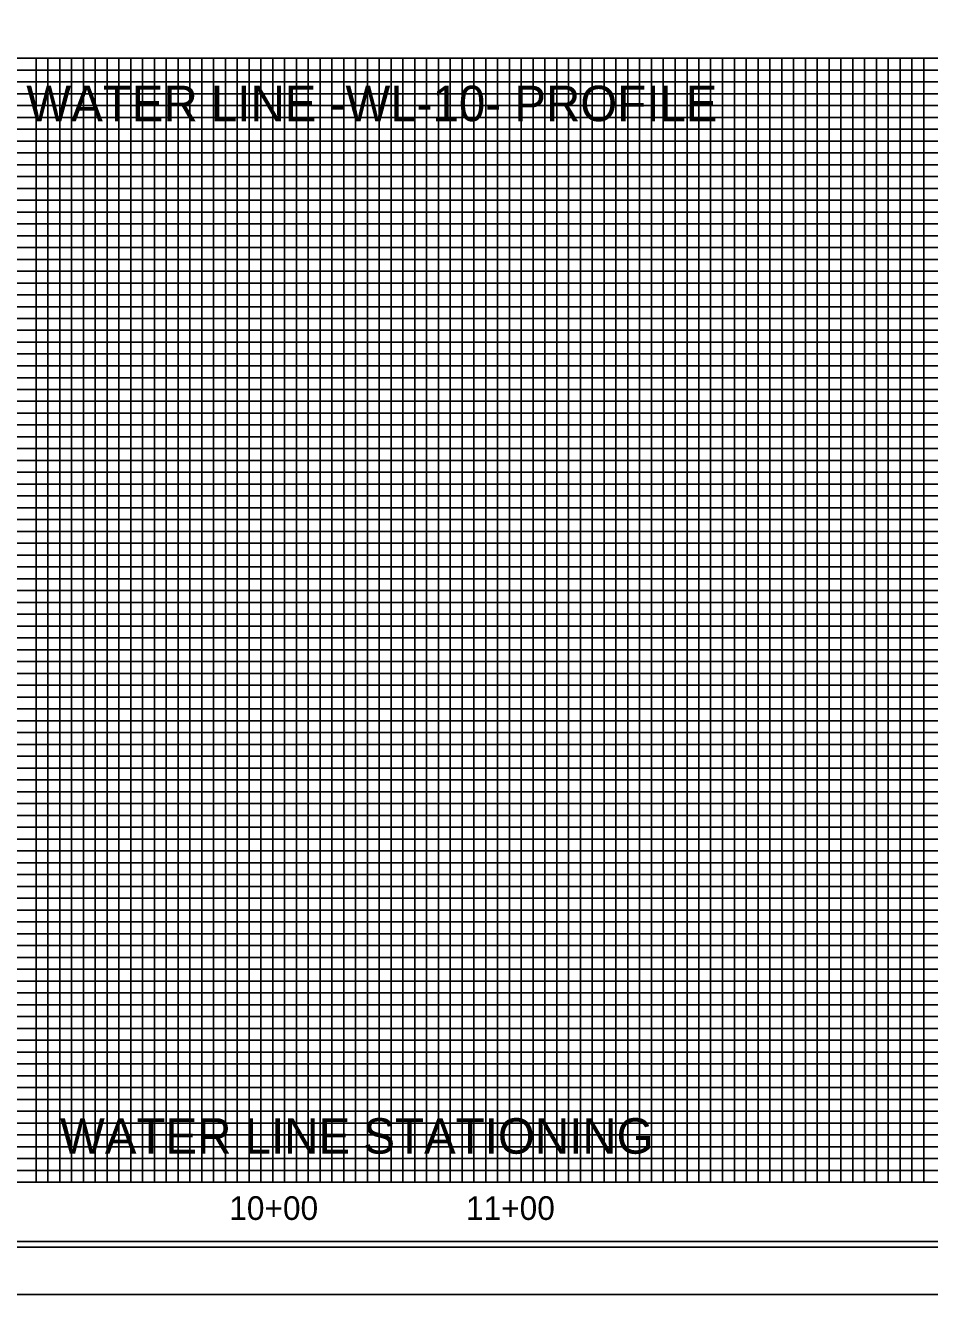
# Model space of a CAD drawing. Extents: x 0 to 4772457, y -312190 to 1506.
# Drawn here: x 1.547 to 2.184, y 0.008 to 0.902 of the extents above; entities that cross this region are included whole.
import ezdxf

# ---------------------------------------------------------------- set-up
doc = ezdxf.new("R2010")
doc.units = 0
for name, color, linetype in [('Exist Mini Skip Lane Lines', 7, 'Continuous'), ('Old_Level_38', 7, 'Continuous'), ('Old_Level_57', 7, 'Continuous'), ('Old_Level_63', 7, 'Continuous'), ('Table of Operation CELL', 7, 'Continuous')]:
    doc.layers.add(name, color=color, linetype=linetype)

msp = doc.modelspace()

# ---------------------------------------------------------------- linework, layer by layer
at = {"layer": 'Exist Mini Skip Lane Lines'}
for p, q in [((0.30499, 0.8375), (2.59666, 0.8375)), ((2.80499, 0.75416), (0.30499, 0.75416)), ((0.30499, 0.67083), (2.80499, 0.67083)), ((2.80499, 0.5875), (0.30499, 0.5875)), ((0.30499, 0.50416), (2.80499, 0.50416)), ((2.80499, 0.42083), (0.30499, 0.42083)), ((0.30499, 0.3375), (2.80499, 0.3375)), ((2.80499, 0.25416), (0.30499, 0.25416)), ((0.30499, 0.17083), (2.80499, 0.17083))]:
    msp.add_line(p, q, dxfattribs=at)
for points in [[(1.59666, 0.0875), (1.59666, 0.87916), (1.67999, 0.87916), (1.67999, 0.0875)], [(1.76333, 0.0875), (1.76333, 0.87916), (1.84666, 0.87916), (1.84666, 0.0875)], [(1.92999, 0.0875), (1.92999, 0.87916), (2.01333, 0.87916), (2.01333, 0.0875)], [(2.09666, 0.0875), (2.09666, 0.87916), (2.17999, 0.87916), (2.17999, 0.0875)]]:
    msp.add_lwpolyline(points, dxfattribs=at)
at = {"layer": 'Old_Level_38'}
for points in [[(0.30499, 0.87916), (2.59666, 0.87916)], [(1.55499, 0.0875), (1.55499, 0.87916), (1.63833, 0.87916), (1.63833, 0.0875)], [(1.72166, 0.0875), (1.72166, 0.87916), (1.80499, 0.87916), (1.80499, 0.0875)], [(1.88833, 0.0875), (1.88833, 0.87916), (1.97166, 0.87916), (1.97166, 0.0875)], [(2.05499, 0.0875), (2.05499, 0.87916), (2.13833, 0.87916), (2.13833, 0.0875)], [(2.80499, 0.79583), (0.30499, 0.79583), (0.30499, 0.7125), (2.80499, 0.7125)], [(2.80499, 0.62916), (0.30499, 0.62916), (0.30499, 0.54583), (2.80499, 0.54583)], [(2.80499, 0.4625), (0.30499, 0.4625), (0.30499, 0.37916), (2.80499, 0.37916)], [(2.80499, 0.29583), (0.30499, 0.29583), (0.30499, 0.2125), (2.80499, 0.2125)], [(2.80499, 0.12916), (0.30499, 0.12916)]]:
    msp.add_lwpolyline(points, dxfattribs=at)
at = {"layer": 'Old_Level_57'}
for points in [[(1.56333, 0.0875), (1.56333, 0.87916), (1.57166, 0.87916), (1.57166, 0.0875)], [(1.57999, 0.0875), (1.57999, 0.87916), (1.58833, 0.87916), (1.58833, 0.0875)], [(1.60499, 0.0875), (1.60499, 0.87916), (1.61333, 0.87916), (1.61333, 0.0875)], [(1.62166, 0.0875), (1.62166, 0.87916), (1.62999, 0.87916), (1.62999, 0.0875)], [(1.64666, 0.0875), (1.64666, 0.87916), (1.65499, 0.87916), (1.65499, 0.0875)], [(1.66333, 0.0875), (1.66333, 0.87916), (1.67166, 0.87916), (1.67166, 0.0875)], [(1.68833, 0.0875), (1.68833, 0.87916), (1.69666, 0.87916), (1.69666, 0.0875)], [(1.70499, 0.0875), (1.70499, 0.87916), (1.71333, 0.87916), (1.71333, 0.0875)], [(1.72999, 0.0875), (1.72999, 0.87916), (1.73833, 0.87916), (1.73833, 0.0875)], [(1.74666, 0.0875), (1.74666, 0.87916), (1.75499, 0.87916), (1.75499, 0.0875)], [(1.77166, 0.0875), (1.77166, 0.87916), (1.77999, 0.87916), (1.77999, 0.0875)], [(1.78833, 0.0875), (1.78833, 0.87916), (1.79666, 0.87916), (1.79666, 0.0875)], [(1.81333, 0.0875), (1.81333, 0.87916), (1.82166, 0.87916), (1.82166, 0.0875)], [(1.82999, 0.0875), (1.82999, 0.87916), (1.83833, 0.87916), (1.83833, 0.0875)], [(1.85499, 0.0875), (1.85499, 0.87916), (1.86333, 0.87916), (1.86333, 0.0875)], [(1.87166, 0.0875), (1.87166, 0.87916), (1.87999, 0.87916), (1.87999, 0.0875)], [(1.89666, 0.0875), (1.89666, 0.87916), (1.90499, 0.87916), (1.90499, 0.0875)], [(1.91333, 0.0875), (1.91333, 0.87916), (1.92166, 0.87916), (1.92166, 0.0875)], [(1.93833, 0.0875), (1.93833, 0.87916), (1.94666, 0.87916), (1.94666, 0.0875)], [(1.95499, 0.0875), (1.95499, 0.87916), (1.96333, 0.87916), (1.96333, 0.0875)], [(1.97999, 0.0875), (1.97999, 0.87916), (1.98833, 0.87916), (1.98833, 0.0875)], [(1.99666, 0.0875), (1.99666, 0.87916), (2.00499, 0.87916), (2.00499, 0.0875)], [(2.02166, 0.0875), (2.02166, 0.87916), (2.02999, 0.87916), (2.02999, 0.0875)], [(2.03833, 0.0875), (2.03833, 0.87916), (2.04666, 0.87916), (2.04666, 0.0875)], [(2.06333, 0.0875), (2.06333, 0.87916), (2.07166, 0.87916), (2.07166, 0.0875)], [(2.07999, 0.0875), (2.07999, 0.87916), (2.08833, 0.87916), (2.08833, 0.0875)], [(2.10499, 0.0875), (2.10499, 0.87916), (2.11333, 0.87916), (2.11333, 0.0875)], [(2.12166, 0.0875), (2.12166, 0.87916), (2.12999, 0.87916), (2.12999, 0.0875)], [(2.14666, 0.0875), (2.14666, 0.87916), (2.15499, 0.87916), (2.15499, 0.0875)], [(2.16333, 0.0875), (2.16333, 0.87916), (2.17166, 0.87916), (2.17166, 0.0875)], [(0.38833, 0.8625), (2.59666, 0.8625), (2.59666, 0.87083), (0.38833, 0.87083)], [(0.38833, 0.84583), (2.59666, 0.84583), (2.59666, 0.85416), (0.38833, 0.85416)], [(0.38833, 0.82083), (2.59666, 0.82083), (2.59666, 0.82916), (0.38833, 0.82916)], [(0.38833, 0.80416), (2.59666, 0.80416), (2.59666, 0.8125), (0.38833, 0.8125)], [(0.38833, 0.77916), (2.72166, 0.77916), (2.72166, 0.7875), (0.38833, 0.7875)], [(0.38833, 0.7625), (2.72166, 0.7625), (2.72166, 0.77083), (0.38833, 0.77083)], [(0.38833, 0.7375), (2.72166, 0.7375), (2.72166, 0.74583), (0.38833, 0.74583)], [(0.38833, 0.72083), (2.72166, 0.72083), (2.72166, 0.72916), (0.38833, 0.72916)], [(0.38833, 0.70416), (2.72166, 0.70416)], [(0.38833, 0.6875), (2.72166, 0.6875), (2.72166, 0.69583), (0.38833, 0.69583)], [(0.38833, 0.6625), (2.72166, 0.6625), (2.72166, 0.67916), (0.38833, 0.67916)], [(0.38833, 0.64583), (2.72166, 0.64583), (2.72166, 0.65416), (0.38833, 0.65416)], [(0.38833, 0.62083), (2.72166, 0.62083), (2.72166, 0.6375), (0.38833, 0.6375)], [(0.38833, 0.60416), (2.72166, 0.60416), (2.72166, 0.6125), (0.38833, 0.6125)], [(0.38833, 0.57916), (2.72166, 0.57916), (2.72166, 0.59583), (0.38833, 0.59583)], [(0.38833, 0.5625), (2.72166, 0.5625), (2.72166, 0.57083), (0.38833, 0.57083)], [(0.38833, 0.5375), (2.72166, 0.5375), (2.72166, 0.55416), (0.38833, 0.55416)], [(0.38833, 0.52083), (2.72166, 0.52083), (2.72166, 0.52916), (0.38833, 0.52916)], [(0.38833, 0.49583), (2.72166, 0.49583), (2.72166, 0.5125), (0.38833, 0.5125)], [(0.38833, 0.47916), (2.72166, 0.47916), (2.72166, 0.4875), (0.38833, 0.4875)], [(0.38833, 0.45416), (2.72166, 0.45416), (2.72166, 0.47083), (0.38833, 0.47083)], [(0.38833, 0.4375), (2.72166, 0.4375), (2.72166, 0.44583), (0.38833, 0.44583)], [(0.38833, 0.4125), (2.72166, 0.4125), (2.72166, 0.42916), (0.38833, 0.42916)], [(0.38833, 0.39583), (2.72166, 0.39583), (2.72166, 0.40416), (0.38833, 0.40416)], [(0.38833, 0.37083), (2.72166, 0.37083), (2.72166, 0.3875), (0.38833, 0.3875)], [(0.38833, 0.35416), (2.72166, 0.35416), (2.72166, 0.3625), (0.38833, 0.3625)], [(0.38833, 0.32916), (2.72166, 0.32916), (2.72166, 0.34583), (0.38833, 0.34583)], [(0.38833, 0.3125), (2.72166, 0.3125), (2.72166, 0.32083), (0.38833, 0.32083)], [(0.38833, 0.2875), (2.72166, 0.2875), (2.72166, 0.30416), (0.38833, 0.30416)], [(0.38833, 0.27083), (2.72166, 0.27083), (2.72166, 0.27916), (0.38833, 0.27916)], [(0.38833, 0.24583), (2.72166, 0.24583), (2.72166, 0.2625), (0.38833, 0.2625)], [(0.38833, 0.22916), (2.72166, 0.22916), (2.72166, 0.2375), (0.38833, 0.2375)], [(0.38833, 0.20416), (2.72166, 0.20416), (2.72166, 0.22083), (0.38833, 0.22083)], [(0.38833, 0.09583), (2.72166, 0.09583), (2.72166, 0.10416), (0.38833, 0.10416), (0.38833, 0.1125), (2.72166, 0.1125), (2.72166, 0.12083), (0.38833, 0.12083), (0.38833, 0.12916), (0.38833, 0.1375), (2.72166, 0.1375), (2.72166, 0.14583), (0.38833, 0.14583), (0.38833, 0.15416), (2.72166, 0.15416), (2.72166, 0.1625), (0.38833, 0.1625), (0.38833, 0.17083), (0.38833, 0.17916), (2.72166, 0.17916), (2.72166, 0.1875), (0.38833, 0.1875), (0.38833, 0.19583), (2.72166, 0.19583)]]:
    msp.add_lwpolyline(points, dxfattribs=at)
at = {"layer": 'Old_Level_63'}
msp.add_line((2.80499, 0.0875), (0.30499, 0.0875), dxfattribs=at)
for points in [[(0.02749, 0.00833), (2.83333, 0.00833), (2.83333, 1.83333), (0.02749, 1.83333)], [(0.04916, 0.04166), (2.82583, 0.04166), (2.82583, 1.8), (0.04916, 1.8)], [(2.80499, 1.79583), (0.30499, 1.79583), (0.30499, 0.04583), (2.80499, 0.04583)], [(0.38833, 0.87916), (2.59666, 0.87916), (2.59666, 0.79583), (2.72166, 0.79583), (2.72166, 0.0875), (0.38833, 0.0875)]]:
    msp.add_lwpolyline(points, close=True, dxfattribs=at)

# ---------------------------------------------------------------- texts
for s, p in [('10+00', (1.691, 0.06092)), ('11+00', (1.85767, 0.06092))]:
    msp.add_text(s, height=0.016667, dxfattribs=at).set_placement(p)
at = {"layer": 'Table of Operation CELL'}
for s, p in [('WATER LINE -WL-10- PROFILE', (1.5481, 0.83479)), ('WATER LINE STATIONING', (1.57184, 0.10758))]:
    msp.add_text(s, height=0.025, dxfattribs=at).set_placement(p)

doc.saveas('drawing.dxf')
